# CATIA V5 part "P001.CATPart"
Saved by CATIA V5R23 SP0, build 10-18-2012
Part number: P001
Definition: Flasque arrière
Bounding box of the stored display mesh (mm): x 28 to 48, y -90 to 400, z -90 to 258
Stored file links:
  C:\wamp\www\COURS\CONCEPTION GMP1\TITRE 02-SEMESTRE 2\03-TP7-PRESSE MECANIQUE\eleve\P001.CATPart
  C:\Documents and Settings\Samuel\Mes documents\Cours\Projet Tutoret\Licence Pro - Presse\Presse\bati_droit.CATPart
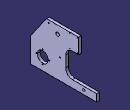
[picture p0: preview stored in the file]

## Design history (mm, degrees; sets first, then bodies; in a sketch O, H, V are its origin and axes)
Body1 (main body)
  Sketch1 on yz-plane, origin (0, 0, 0), H (0, 1, 0), V (0, 0, 1)
    line L1 (-90, -90) -> (-90, 90)
    line L2 (-90, 90) -> (27.6349, 258)
    line L3 (27.6349, 258) -> (266, 258)
    line L4 (266, 258) -> (266, 146)
    line L5 (266, 146) -> (220, 146)
    line L6 (170, 96) -> (170, 14)
    line L7 (220, -36) -> (400, -36)
    line L8 (400, -36) -> (400, -90)
    line L9 (400, -90) -> (-90, -90)
    circle A1 centre (110, 200) radius 12.5
    point P8 (110, 200)
    circle A2 centre (0, 0) radius 40
    arc A3 centre (220, 96) radius 50 from (220, 146) to (170, 96) ccw
    arc A4 centre (220, 14) radius 50 from (170, 14) to (220, -36) ccw
    distance L9 H = 90
    length L8 = 54
    length L4 = 112
    radius A1 = 12.5
    radius A2 = 40
    radius A3 = 50
    radius A4 = 50 {= Sketch1.radius(A3)}
    angle L2 L1 = 145
    length L1 = 180
    distance P8 L3 = 58
    distance L4 P8 = 156
    distance L1 L4 = 356
    distance L3 L9 = 348
    distance V L6 = 170
    distance V L1 = 90
    distance L8 V = 400
    vertical: L1 V, L4 V, L6 V, L8 V
    horizontal: L3 H, L5 H, L7 H, L9 H
    tangency: A3 L5, A3 L6, A4 L6, A4 L7
  Pad1: profile Sketch1, direction (1, 0, 0), length 48, opposite side length -28
  Sketch2 on face of Pad1, origin (48, 7.1381, 64.7488), H (0, 1, 0), V (0, 0, 1)
    point P1 (-7.1381, -16.7488)
    reference intersected line E1 through (-7.1381, 0) direction (0, 1) from zx-plane
    reference projected point E2 (-7.1381, -64.7488) from axis of face of Pad1
    distance P1 E2 = 48
    coincidence: P1 E1
  Hole1: placed by Sketch2, at (48, 0, 48) direction (-1, 0, 0), diameter 6.647, through (limit type 3), threaded "M8", thread diameter 8, thread depth 10, pitch 1.25
  CircPattern1: of Hole1, instances 4, angular step 90, axis from face of Pad1
  Sketch3 on face of Pad1, origin (48, 94.8501, 259.7518), H (0, 1, 0), V (0, 0, 1)
    point P1 (-50.8501, -21.7518)
    reference projected line E1 (171.1499, -1.7518) -> (-67.2153, -1.7518) from edge [face of Pad1 | face of Pad1]
    reference projected line E2 (171.1499, -113.7518) -> (171.1499, -1.7518) from edge [face of Pad1 | face of Pad1]
    distance P1 E1 = 20
    distance P1 E2 = 222
  Hole2: placed by Sketch3, at (48, 44, 238) direction (-1, 0, 0), diameter 6.647, through (limit type 3), threaded "M8", thread diameter 8, thread depth 10, pitch 1.25
  Sketch4 on face of Pad1, origin (48, 125.9711, 40.7234), H (0, 1, 0), V (0, 0, 1)
    point P1 (2.0289, 19.2766)
    reference projected line E1 (-215.9711, -130.7234) -> (274.0289, -130.7234) from edge [face of Pad1 | face of Pad1]
    reference projected line E2 (-215.9711, 49.2766) -> (-215.9711, -130.7234) from edge [face of Pad1 | face of Pad1]
    distance P1 E1 = 150
    distance P1 E2 = 218
  Hole3: placed by Sketch4, at (48, 128, 60) direction (-1, 0, 0), diameter 8, through (limit type 3)
  Sketch5 on face of Pad1, origin (28, 216.0957, 228.8991), H (0, 1, 0), V (0, 0, -1)
    point P1 (41.9043, -23.1009)
    reference projected line E1 (49.9043, 82.8991) -> (49.9043, -29.1009) from edge [face of Pad1 | face of Pad1]
    reference projected line E2 (49.9043, -29.1009) -> (-188.4609, -29.1009) from edge [face of Pad1 | face of Pad1]
    distance P1 E1 = 8
    distance P1 E2 = 6
  Hole4: placed by Sketch5, at (28, 258, 252) direction (1, 0, 0), diameter 6, through (limit type 3)
  RectPattern1: of Hole4, direction 1 instances 2, spacing 58, along face of Pad1 reversed, direction 2 instances 2, spacing 100, along face of Pad1
  Sketch6 on face of Pad1, origin (48, 361.3705, -70.2612), H (0, 1, 0), V (0, 0, 1)
    point P1 (-57.3705, 10.2612)
    reference projected line E1 (38.6295, -19.7388) -> (38.6295, 34.2612) from edge [face of Pad1 | face of Pad1]
    reference projected line E2 (-451.3705, -19.7388) -> (38.6295, -19.7388) from edge [face of Pad1 | face of Pad1]
    distance P1 E1 = 96
    distance P1 E2 = 30
  Hole5: placed by Sketch6, at (48, 304, -60) direction (-1, 0, 0), diameter 16, through (limit type 3)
